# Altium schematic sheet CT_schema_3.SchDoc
size 143 x 123 mm
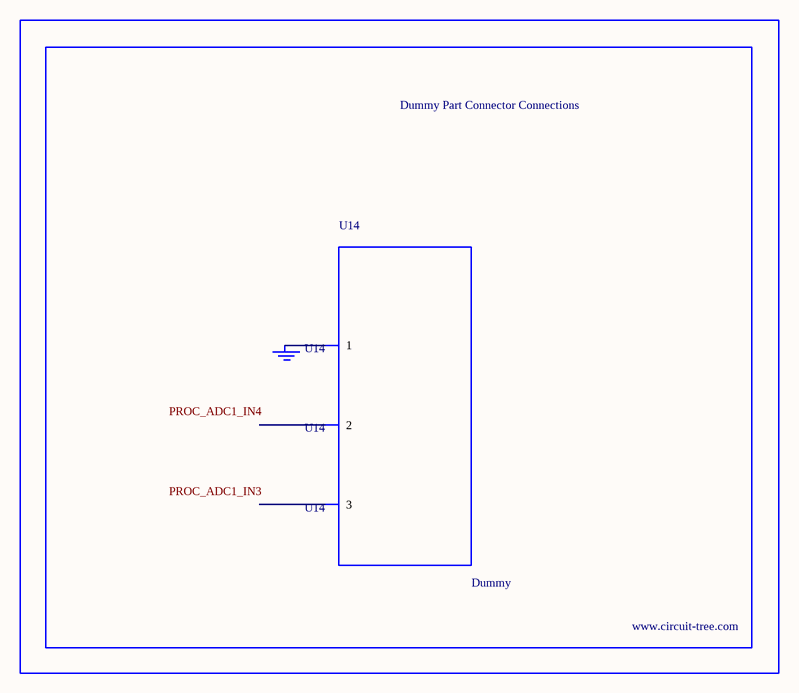
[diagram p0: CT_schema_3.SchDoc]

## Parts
BORDER2  (no value)
GND_INSTANCE_2_0  (no value)
U14  Dummy  [DUMMY_PACKAGE_113]

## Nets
NetGND_INSTANCE_2_0_0: GND_INSTANCE_2_0.0(GND) U14.1

Not connected (* = marked no-connect by the designer): U14 2 3

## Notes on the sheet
- Labels drawn without touching a wire or pin: PROC_ADC1_IN3, PROC_ADC1_IN4

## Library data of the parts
BORDER2 = BORDER_PAGE2
GND_INSTANCE_2_0 = GND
